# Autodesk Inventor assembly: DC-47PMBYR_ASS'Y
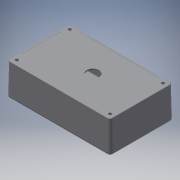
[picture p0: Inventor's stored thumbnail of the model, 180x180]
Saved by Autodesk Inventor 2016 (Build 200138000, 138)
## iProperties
Created: 2010-08
Part Number: DC-47PMBYR_ASS'Y
Description: STEP AP214
Document SubType Name: Assembly
Designer: irish_000
Sending System: SolidWorks 2010
Preprocessor: SwSTEP 2.0
Title: DC-47PMBYR_ASS'Y.STEP
Revision Number: ANY
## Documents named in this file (4)
- C:\Users\irish_000\Google Drive\School Files\Fall 2015\Make Course\Project files\The box\DC-47PMBYR_ASS'Y.iam
- C:\Users\irish_000\Google Drive\School Files\Fall 2015\Make Course\Project files\The box\SCREWS-DC-BR.ipt
- C:\Users\irish_000\Google Drive\School Files\Fall 2015\Make Course\Project files\The box\DC-47C_DC-47C-R.ipt
- C:\Users\irish_000\Google Drive\School Files\Fall 2015\Make Course\Project files\The box\DC-47B_DC-47BPMBY.ipt
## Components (6 placed, 6 different names)
1. SCREWS-DC-BR_1
2. SCREWS-DC-BR_2
3. SCREWS-DC-BR_3
4. SCREWS-DC-BR_4
5. DC-47C_DC-47C-R_5
6. DC-47B_DC-47BPMBY_6
